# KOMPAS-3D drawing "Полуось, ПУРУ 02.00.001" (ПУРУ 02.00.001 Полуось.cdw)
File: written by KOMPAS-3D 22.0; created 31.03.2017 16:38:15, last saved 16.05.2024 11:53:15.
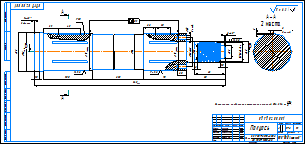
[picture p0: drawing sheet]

Sheet 1: A4x3, landscape

Document properties: Масса: 17.1612; Автор: cons; Полное имя файла: D:\Вован\Антиград\Град\12.02.2025\ПУРУ 02.00.000 Ось\Чертежи\ПУРУ 02.00.001 Полуось.cdw; Знак неуказанной шероховатости: 4; Параметр неуказанной шероховатости: Ra 6,3; Форматы листов документа: A4@4~3

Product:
- Body: Тело 1
    Материал: Круг$d85 ГОСТ 2590-2006;20 ГОСТ 1050-88$ (density 0 kg/m3)
- Body: Тело 2
    Материал: Круг$d85 ГОСТ 2590-2006;20 ГОСТ 1050-88$ (density 0 kg/m3)
- Part/product: Полуось  | designation ПУРУ 02.00.001
    Материал: Круг$d85 ГОСТ 2590-2006;20 ГОСТ 1050-88$ (density 7859 kg/m3)
    Масса: 17.1612
    Раздел спецификации: Детали
    Форматы листов документа: A4@4~3
- Part/product: (unnamed)  | designation 1
- Part/product: (unnamed)  | designation 2
- Part/product: (unnamed)  | designation 3

Title block, sheet 1: Наименование: Полуось; designation: ПУРУ 02.00.001; Материал: Круг 85 ГОСТ 2590-2006 20 ГОСТ 1050-88; Масса: 17,2; Количество листов документа: 1; organisation: ООО "НПЦ"Антиград"; Форматы листов документа: A4 3; Литера: А; stored path: D:\РУ 00.00.000 Установка противоградовая ручная\РУ 02.00.000 Ось\РУ 02.00.001 Полуось.cdw; Разработал: Грицунов; Проверил: Налоева; Т. контр.: Семеновский; Н. контр.: Абшаев А.М.; Разработал, date: 04.04.2017; Проверил, date: 04.04.2017; Т. контр., date: 04.04.2017; Н. контр., date: 04.04.2017

Views: Вид 1, Местный разрез 1, Местный разрез 2, Местный разрез 3, Спереди, Разрез А-А, Разрез 3
Referenced files in D:\Вован\Антиград\Град\ПУРУ 00.00.000 Установка пусковая ручная Элия-Р\ПУРУ 02.00.000 Ось\: ПУРУ 02.00.001 Полуось.m3d
Referenced files in D:\Град\ПУРУ 00.00.000 Установка пусковая ручная Элия-Р\ПУРУ 02.00.000 Ось\: ПУРУ 02.00.001 Полуось.m3d
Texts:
  Ra 1,6
  Ra 3,2
  Ra 6,3
  Ra 6,3 ( )
  ПУРУ 02.00.001 Полуось
Dimensions and other numbers on the sheet: 79; 82; 28; 40; 45; 78; 74; 2; 1; 3 фаски; 10; 80; 63; 90; 255; 100; 545; 0,1; 31; 50; 26; 30; 2 отв.; 20; 60±0,2; 6; 33; 2 места; 6 пазов; 1:1; 17,2; 04.04.2017

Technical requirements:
  Неуказанные предельные отклонения размеров: H14, h14,    IT14 2 .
